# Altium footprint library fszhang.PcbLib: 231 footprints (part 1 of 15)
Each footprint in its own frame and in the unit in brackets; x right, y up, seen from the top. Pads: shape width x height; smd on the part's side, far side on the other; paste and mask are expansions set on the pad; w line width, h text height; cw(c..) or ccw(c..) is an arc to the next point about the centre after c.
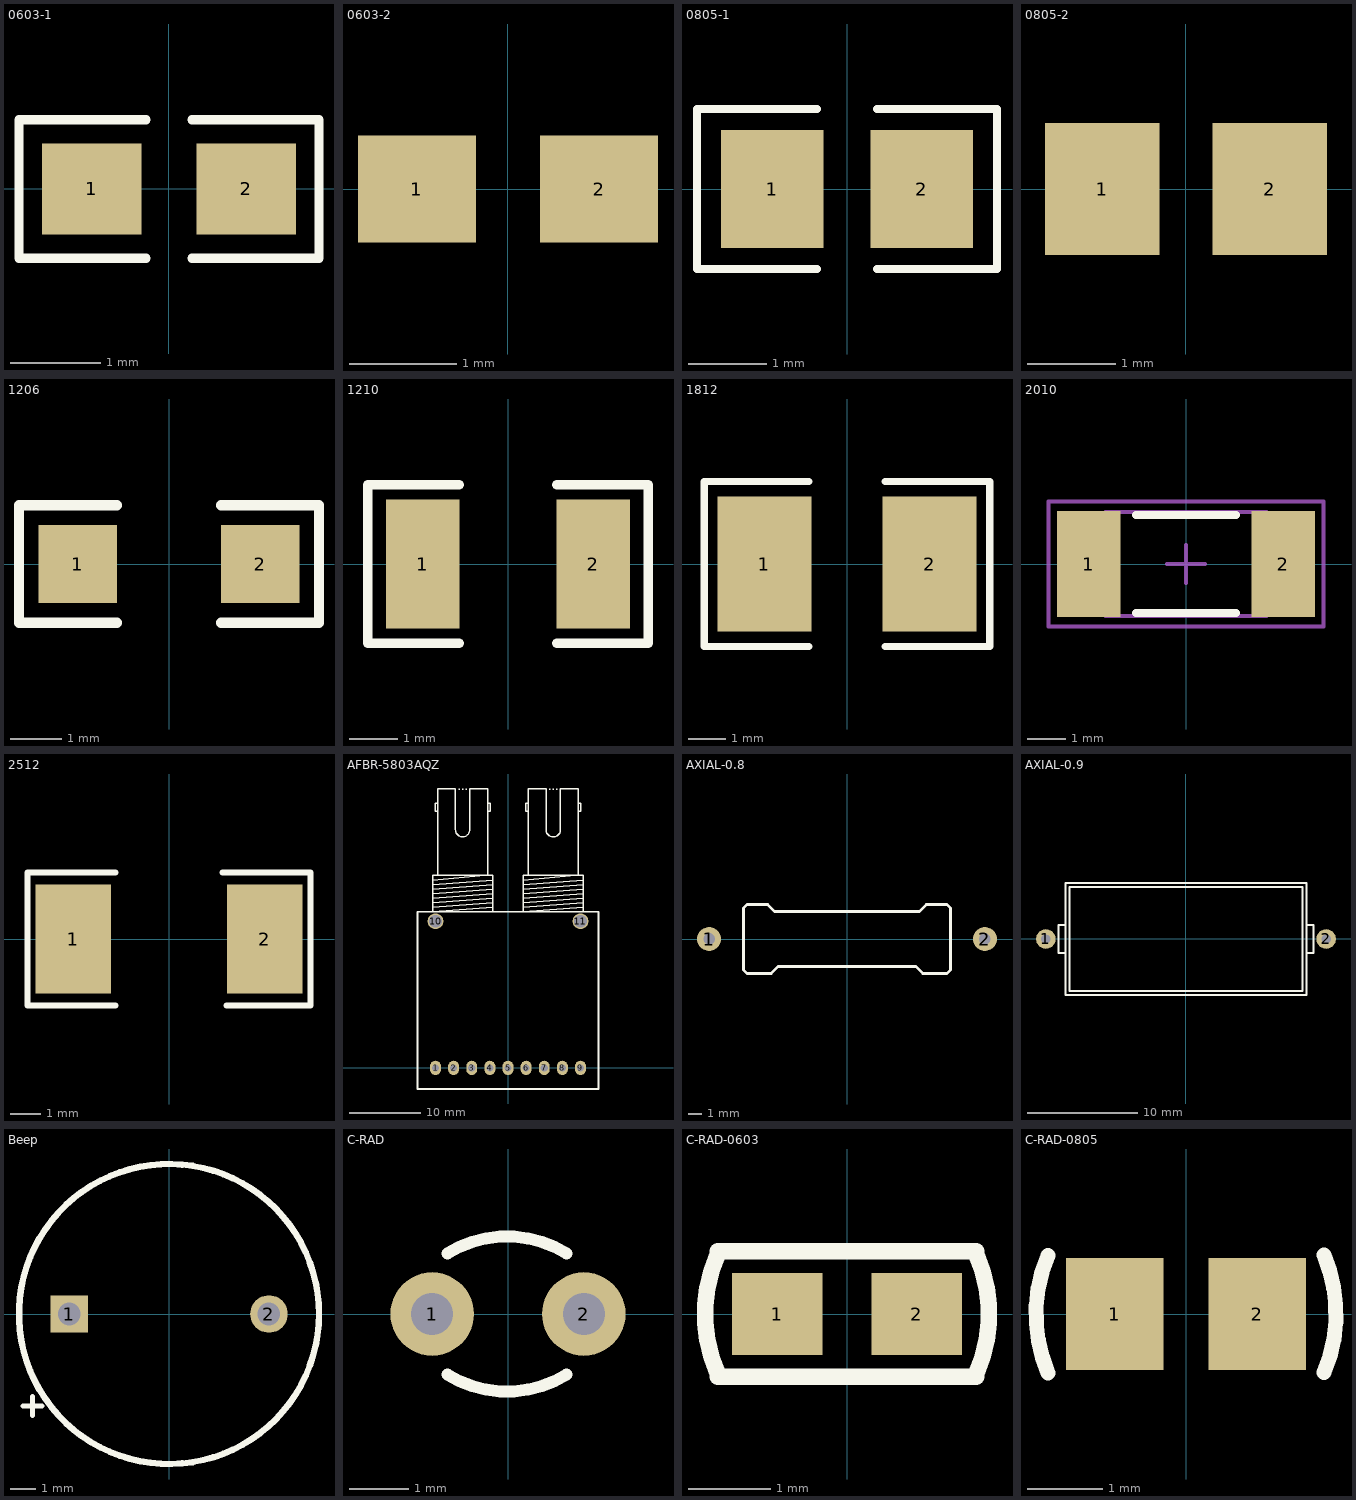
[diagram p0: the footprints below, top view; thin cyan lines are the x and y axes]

## 0603-1 [mm] "贴片带丝印"
height 0.6
pads (2):
  rect 1.1x1 smd: 1(-0.85,0) 2(0.85,0)
Top Overlay:
  lines w0.1: -0.254,-0.762 -1.651,-0.762 -1.651,0.762 -0.254,0.762 ; 0.254,-0.762 1.651,-0.762 1.651,0.762 0.254,0.762
3D body: height 1, standoff 0, extent -1.143,-0.381 1.143,0.381

## 0603-2 [mm] "贴片无丝印"
height 0.6
pads (2):
  rect 1.1x1 smd: 1(-0.85,0) 2(0.85,0)

## 0805-1 [mm] "贴片带丝印"
height 1.1
pads (2):
  rect 1.3x1.5 smd: 1(-0.95,0) 2(0.95,0)
Top Overlay:
  lines w0.1: -0.381,-1.016 -1.905,-1.016 -1.905,1.016 -0.381,1.016 ; 0.381,-1.016 1.905,-1.016 1.905,1.016 0.381,1.016
3D body: height 1, standoff 0, extent -1.143,-0.508 -1.016,0.508
3D body: height 1, standoff 0, extent 1.016,-0.508 1.143,0.508
3D body: height 1, standoff 0, extent -1.016,-0.508 1.016,0.508

## 0805-2 [mm] "贴片无丝印"
height 1
pads (2):
  rect 1.3x1.5 smd: 1(-0.95,0) 2(0.95,0)

## 1206 [mil] "贴片元件"
height 59.06
pads (2):
  rect 60x60 smd: 1(-70,0) 2(70,0)
Top Overlay:
  lines w7.87: -40,-45 -115,-45 -115,45 -40,45 ; 40,-45 115,-45 115,45 40,45
3D body: height 39.37, standoff 0, extent -55,-35 55,35
3D body: height 39.37, standoff 0, extent 55,-35 75,35
3D body: height 39.37, standoff 0, extent -75,-35 -55,35

## 1210 [mil] "贴片元件"
height 59.06
pads (2):
  rect 60x106.3 smd: 1(-70,0) 2(70,0)
Top Overlay:
  lines w7.87: -40,-65 -115,-65 -115,65 -40,65 ; 40,-65 115,-65 115,65 40,65
3D body: height 39.37, standoff 0, extent -65,-50 65,50

## 1812 [mm] "保险丝"
height 1
pads (2):
  rect 2.5x3.6 smd: 1(-2.2,0) 2(2.2,0)
Top Overlay:
  lines w0.2: -1.016,-2.2 -3.81,-2.2 -3.81,2.2 -1.016,2.2 ; 1.016,-2.2 3.81,-2.2 3.81,2.2 1.016,2.2
3D body: height 1.2, standoff 0, extent -2.286,-1.651 2.286,1.651
3D body: height 0.9, standoff 0, extent 2.159,0.635 2.667,1.524
3D body: height 0.9, standoff 0, extent 2.159,-1.524 2.667,-0.635
3D body: height 0.9, standoff 0, extent -2.54,-1.524 -2.032,-0.635
3D body: height 0.9, standoff 0, extent -2.54,0.635 -2.032,1.524

## 2010 [mm] "贴片电阻"
height 0.6
pads (2):
  rect 1.65x2.75 smd: 1(-2.525,0) 2(2.525,0)
Top Overlay:
  lines w0.2: -1.3,-1.275 1.3,-1.275 ; -1.3,1.275 1.3,1.275
Mechanical 13:
  lines w0.1: -2.1,-1.35 -2.1,1.35 2.1,1.35 2.1,-1.35 -2.1,-1.35
Mechanical 15:
  lines w0.1: -0.5,0 0.5,0 ; 0,-0.5 0,0.5 ; -3.575,-1.625 -3.575,1.625 3.575,1.625 3.575,-1.625 -3.575,-1.625
3D body: height 0.6, standoff 0, extent -2.1,-1.35 2.1,1.35

## 2512 [mm] "保险丝"
height 1
pads (2):
  rect 2.5x3.6 smd: 1(-3.175,0) 2(3.175,0)
Top Overlay:
  lines w0.2: -1.778,-2.2 -4.699,-2.2 -4.699,2.2 -1.778,2.2 ; 1.778,2.2 4.699,2.2 4.699,-2.2 1.905,-2.2
3D body: height 1.2, standoff 0, extent -3.175,-1.651 3.175,1.651
3D body: height 0.9, standoff 0, extent -2.54,0.635 -2.032,1.524
3D body: height 0.9, standoff 0, extent -2.54,-1.524 -2.032,-0.635
3D body: height 0.9, standoff 0, extent 2.159,-1.524 2.667,-0.635
3D body: height 0.9, standoff 0, extent 2.159,0.635 2.667,1.524

## AFBR-5803AQZ [mm] "光以太网"
height 14.8
pads (11):
  oval 1.524x2 hole 1: 1(-10.16,0) 2(-7.62,0) 3(-5.08,0) 4(-2.54,0) 5(0,0) 6(2.54,0) 7(5.08,0) 8(7.62,0) 9(10.16,0)
  round 2.2 hole 1.8: 10(-10.16,20.54) 11(10.16,20.54)
Top Overlay:
  lines w0.2: -10.559,23.15 -2.159,23.785 ; -10.559,23.785 -2.159,24.42 ; -10.559,24.42 -2.159,25.055 ; -10.559,25.055 -2.159,25.69 ; -10.559,25.69 -2.159,26.325 ; -10.559,26.325 -3.184,26.98 ; -10.55,22.515 -2.159,23.15 ; -9.859,35.985 -10.225,35.985 -10.225,37.085 -9.859,37.085 ; -7.359,33.378 ccw(c-6.359,33.378) -5.359,33.385 -5.359,39.08 -2.859,39.08 -2.859,26.98 -9.859,26.98 -9.859,39.08 -7.359,39.08 -7.359,33.378 ; -6.923,39.047 -6.796,39.047 ; -6.415,39.047 -6.288,39.047 ; -5.907,39.047 -5.78,39.047 ; -2.859,35.985 -2.478,35.985 -2.478,37.085 -2.859,37.085 ; -2.168,22.515 -10.559,21.88 ; 2.141,23.15 10.541,23.785 ; 2.141,23.785 10.541,24.42 ; 2.141,24.42 10.541,25.055 ; 2.141,25.055 10.541,25.69 ; 2.141,25.69 10.541,26.325 ; 2.141,26.325 9.516,26.98 ; 2.15,22.515 10.541,23.15 ; 2.841,35.985 2.475,35.985 2.475,37.085 2.841,37.085 ; 5.341,33.378 ccw(c6.341,33.378) 7.341,33.385 7.341,39.08 9.841,39.08 9.841,26.98 2.841,26.98 2.841,39.08 5.341,39.08 5.341,33.378 ; 5.777,39.047 5.904,39.047 ; 6.285,39.047 6.412,39.047 ; 6.793,39.047 6.92,39.047 ; 9.841,35.985 10.222,35.985 10.222,37.085 9.841,37.085 ; 10.532,22.515 2.141,21.88 ; -10.559,21.88 -10.559,26.98 -2.159,26.98 -2.159,21.88 -10.559,21.88 ; 2.141,21.88 2.141,26.98 10.541,26.98 10.541,21.88 2.141,21.88
  lines w0.254: -12.7,-2.965 12.7,-2.965 ; -12.7,-2.92 -12.7,21.88 12.7,21.88 12.7,-2.92

## AXIAL-0.8 [mil] "插件电阻"
height 100
pads (2):
  round 70 hole 33.46: 1(-400,0) 2(400,0)
Top Overlay:
  lines w7.87: -300,-90 -300,90 -290,100 -230,100 -210,80 210,80 230,100 290,100 300,90 300,-90 290,-100 220,-100 200,-80 -200,-80 -220,-100 -290,-100 -300,-90
3D body: height 196.07, standoff 0, extent -295,-96.82 -216.26,99.64
3D body: height 196.07, standoff 0, extent 216.26,-96.82 295,99.64
3D body: height 176.54, standoff 19.68, extent -216.53,-77.17 216.54,80
3D body: height 106.24, standoff 90.55, extent -405.24,-6.44 -295,9.27
3D body: height 106.24, standoff 90.55, extent 295,-6.44 405.24,9.27
3D body: height 98.43, standoff 0, extent 392.2,-7.85 407.88,7.87
3D body: height 98.43, standoff 0, extent -407.81,-7.85 -392.12,7.86

## AXIAL-0.9 [mil] "插件电阻"
height 100
pads (2):
  round 70 hole 33.46: 1(-500,0) 2(500,0)
Top Overlay:
  lines w7.87: -430,-50 -455,-50 -455,50 -430,50 ; 430,-50 455,-50 455,50 430,50 ; -430,-200 -430,200 430,200 430,-200 -430,-200 ; -415,-185 -415,185 415,185 415,-185 -415,-185

## Beep [mm] "蜂鸣器"
height 6
pads (2):
  rect 1.5x1.5 hole 0.9: 1(-4,0)
  round 1.5 hole 0.9: 2(4,0)
Top Overlay:
  circle w0.254: c0,0 r6
  lines w0.2: -5.842,-3.683 -5.08,-3.683 ; -5.461,-4.064 -5.461,-3.302

## C-RAD [mm] "瓷片电容"
height 6
pads (2):
  round 1.4 hole 0.7: 1(-1.27,0) 2(1.27,0)
Top Overlay:
  lines w0.2: -1.016,-1.016 ccw(c-0.018,0.606) 0.981,-1.016 ; -1.016,1.016 cw(c-0.018,-0.606) 0.981,1.016

## C-RAD-0603 [mm] "贴片电容"
height 0.6
pads (2):
  rect 1.1x1 smd: 1(-0.85,0) 2(0.85,0)
Top Overlay:
  lines w0.2: -1.574,-0.762 1.574,-0.762 ; -1.574,-0.727 cw(c0.048,0) -1.574,0.727 ; -1.574,0.762 1.574,0.762 ; 1.574,-0.727 ccw(c-0.048,0) 1.574,0.727
3D body: height 1, standoff 0, extent -1.143,-0.381 1.143,0.381

## C-RAD-0805 [mm] "贴片电容"
height 1
pads (2):
  rect 1.3x1.5 smd: 1(-0.95,0) 2(0.95,0)
Top Overlay:
  lines w0.2: -1.842,0.779 ccw(c0,0) -1.838,-0.789 ; 1.838,0.789 cw(c0,0) 1.842,-0.779
3D body: height 0.9, standoff 0, extent 0.889,-0.635 1.27,0.635
3D body: height 0.9, standoff 0, extent -1.27,-0.635 -0.889,0.635
3D body: height 0.8, standoff 0, extent -1.016,-0.635 1.016,0.635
